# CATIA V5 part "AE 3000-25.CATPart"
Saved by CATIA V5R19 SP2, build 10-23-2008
Part number: AE 3000-25
Bounding box of the stored display mesh (mm): x -47.487 to 47.487, y -47.487 to 47.487, z 0 to 120
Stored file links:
  C:\Users\Bora\Desktop\3D Katı model\AE serisi\AE 3000\AE 3000-25.CATPart
  C:\Program Files\Dassault Systemes\B19\intel_a\reffiles\standard\MetricThickPitch.txt
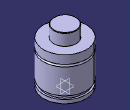
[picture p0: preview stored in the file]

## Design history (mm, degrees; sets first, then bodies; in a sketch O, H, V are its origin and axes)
Body1 (main body)
  Sketch1 on yz-plane, origin (0, 0, 0), H (0, 1, 0), V (0, 0, 1)
    point P1 (47.5, 75.5)
    point P5 (25, 119)
    point P7 (25, 119)
    point P12 (47.5, 70.5)
    point P13 (47.5, 75.5)
    point P14 (47.5, 70.5)
    line L1 (47.5, 75.5) -> (47.5, 94)
    line L2 (47.5, 0) -> (47.5, 8)
    arc A1 centre (24, 119) radius 1 from (25, 119) to (24, 120) ccw
    line L3 (25, 119) -> (25, 94)
    line L4 (43.5, 15) -> (43.5, 8)
    line L5 (47.5, 15) -> (47.5, 70.5)
    arc A2 centre (47.5, 73) radius 2.5 from (47.5, 75.5) to (47.5, 70.5) ccw
    line L6 (24, 120) -> (0, 120)
    point P15 (0, 120)
    line L7 (25, 94) -> (47.5, 94)
    line L8 (0, 0) -> (47.5, 0)
    line L9 (43.5, 15) -> (47.5, 15)
    line L10 (43.5, 8) -> (47.5, 8)
    tangency: L6 A1
    coincidence: P15 V, P1 P13, P5 P7, P12 P14
    horizontal: L7 H, L8 H, L9 H, L10 H
  Shaft1: profile Sketch1, axis Sketch1.V, angle 360
  Sketch2 on face of Shaft1 from Sketch1.L8, origin (0, 0, 0), H (1, 0, 0), V (0, -1, 0)
    point P1 (30, 0)
    distance P1 V = 30
  Hole1: placed by Sketch2, at (30, 0, 0) direction (0, 0, 1), diameter 6.647, depth 13, threaded "M8", thread diameter 8, thread depth 13, pitch 1.25
  CircPattern1: of Hole1, instances 4, angular step 90, axis from xy-plane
